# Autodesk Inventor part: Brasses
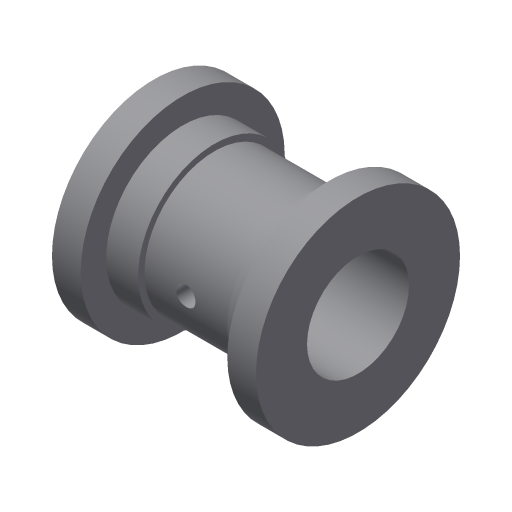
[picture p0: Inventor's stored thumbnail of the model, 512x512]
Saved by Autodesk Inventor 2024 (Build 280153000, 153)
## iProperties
Created: 2009-04
Part Number: Brasses
Document SubType Name: Modeling
Designer: Sham
Density: 1 g/cm^3
Material: Generic
Appearance: Default
Author: Sham
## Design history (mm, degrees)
sketch "Sketch1"
  geometry: L1 (0, 32)-(9, 32); L2 (0, 16)-(64, 16); L3 (64, 32)-(55, 32); L4 (55, 32)-(55, 24); L5 (55, 24)-(47, 24); L6 (19, 22)-(47, 22); L7 (47, 24)-(47, 22); L8 (19, 22)-(19, 24); L9 (19, 24)-(9, 24); L10 (9, 24)-(9, 32); L11 (0, 32)-(0, 16); L12 (64, 32)-(64, 16); L13 (-12.8, 0)-(76.8, 0) reference; 1 further point
  constraints: 24 end point, 7 parallel, 4 perpendicular, 1 collinear, 1 horizontal, 1 vertical alignment, 1 other
  dimensions: "d0" = 9 distance of L1.start L1.end; "d2" = 16 distance from line of L2 point (0, 0); "d3" = 64 distance of L2.start L2.end; "d4" = 24 distance from line of point (0, 0) L5; "d5" = 28 distance of L6.start L6.end; "d6" = 22 distance from line of point (0, 0) L6; "d7" = 8 distance of L4.end L5.end
revolve "Revolution1" sketch "Sketch1" stored, may be unused: angle "d8" = 90 deg
workplane "Work Plane1"
sketch "Sketch2"
  geometry: C1 r 4 at (-32, 0)
  constraints: 1 centre point
  dimensions: "d10" = 8 diameter of C1
extrude "Extrusion1" join sketch "Sketch2" stored distance "d11" = 10; taper "d12" = 0 deg
sketch "Sketch3"
  geometry: C1 r 4 at (0, 0) reference; C2 r 3 at (0, 0)
  constraints: 1 centre point, 1 coincident
  dimensions: "d13" = 6 diameter of C2
extrude "Extrusion2" cut sketch "Sketch3" extent not by distance; stored distance "d14" = 10; taper "d15" = 0 deg
body "Solid1"
